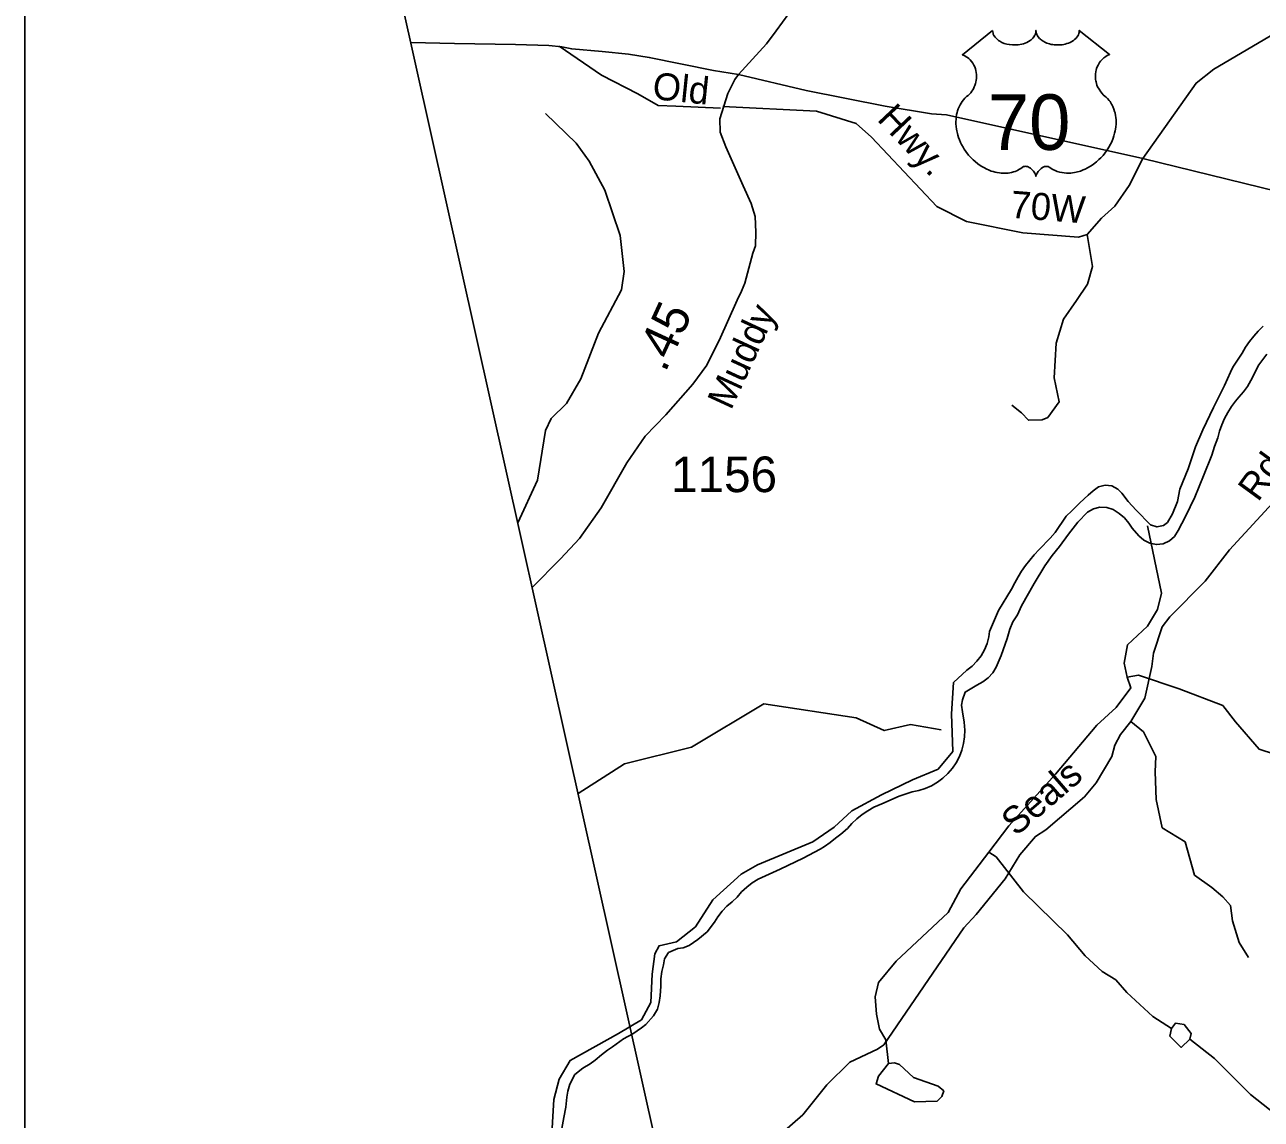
# Model space of a CAD drawing. Extents: x 1113032 to 1302912, y 664689 to 832535.
# Drawn here: x 1147669 to 1152008, y 722592 to 726434 of the extents above; entities that cross this region are included whole.
import ezdxf

# ---------------------------------------------------------------- set-up
doc = ezdxf.new("R2010")
doc.units = 0
for name, color, linetype in [('Exist Boundary Political CountyLine', 7, 'Continuous'), ('Exist Hydrographic Creek Single Shore', 7, 'Continuous'), ('Exist Hydrographic Misc Water Feature', 7, 'Continuous'), ('Exist Hydrographic River Shore', 7, 'Continuous'), ('Exist Road Non-System Type 51', 7, 'Continuous'), ('Exist Road Non-System Type 51 Label', 7, 'Continuous'), ('Exist Road Primary US Attributed', 7, 'Continuous'), ('Exist Road Primary US Shield CELL', 7, 'Continuous'), ('Exist Road Primary US Shield Number Label', 7, 'Continuous'), ('Exist Road Secondary Mileage Hundredths English Label', 7, 'Continuous'), ('Exist Road Secondary Type 51 Attributed', 7, 'Continuous'), ('Exist Road Secondary Type 51 Label', 7, 'Continuous'), ('Exist Road Secondary Type 51 Number Label', 7, 'Continuous'), ('Map Preparation Inset Cut Line', 7, 'Continuous')]:
    doc.layers.add(name, color=color, linetype=linetype)

msp = doc.modelspace()

# ---------------------------------------------------------------- linework, layer by layer
at = {"layer": 'Exist Boundary Political CountyLine'}
msp.add_lwpolyline([(1148404.8, 729149.7), (1156119.1, 694505), (1156385.7, 693318.6), (1156931.2, 691025.8), (1157283.7, 689488.8), (1157952.7, 686675.9), (1158627.6, 683719.1), (1158926.2, 682391.3), (1158990.6, 682053.6), (1159297.9, 680748.3), (1159630.3, 679269.8), (1159949.4, 677817.9), (1160303.4, 676324.9), (1160338.1, 676139.7)], dxfattribs=at)
at = {"layer": 'Exist Hydrographic Creek Single Shore'}
msp.add_lwpolyline([(1149610.4, 723735.3), (1149773.4, 723839.7), (1150008.4, 723897.4), (1150262.3, 724049.9), (1150586.3, 724000.7), (1150685.3, 723956.1), (1150777.3, 723977.2), (1150885.4, 723958.6)], dxfattribs=at)
at = {"layer": 'Exist Hydrographic Misc Water Feature'}
for points in [[(1149496.1, 726121.6), (1149603.3, 726018.5), (1149649.5, 725954.3), (1149704.8, 725853.2), (1149758.3, 725693.7), (1149772.7, 725567.1), (1149762.8, 725503.2), (1149682.5, 725351.4), (1149620, 725191), (1149569.4, 725104.2), (1149515.9, 725051.9), (1149496.8, 725008.9), (1149467.8, 724835.4), (1149399, 724685)], [(1151609.1, 724675.3), (1151658, 724438.7), (1151644.3, 724381.5), (1151608.7, 724322.3), (1151538.8, 724256.5), (1151527, 724192.7), (1151537.6, 724144.1)], [(1151537.6, 724144.1), (1151550.5, 724106.1), (1151498.6, 724037.4), (1151430.7, 723974.7), (1151285.7, 723802.8), (1151122.5, 723621.5), (1151051.9, 723529.4)], [(1152054.3, 723873.6), (1152000.8, 723891.1), (1151917.4, 723987.1), (1151873, 724044.6), (1151720.4, 724102.7), (1151577.8, 724150.7), (1151537.6, 724144.1)], [(1150700.6, 722787.2), (1150691, 722871.1), (1150668, 722907.6), (1150657.5, 722960.4), (1150653.3, 723022), (1150664.6, 723071.8), (1150726.8, 723146.1), (1150909.8, 723317.2), (1150954.2, 723400), (1151051.9, 723529.4)], [(1151692.8, 722910.9), (1151627.9, 722952.4), (1151536.2, 723037.1), (1151497.5, 723080.6), (1151450.3, 723110.2), (1151389.8, 723165.6), (1151327.9, 723239), (1151174.1, 723389.9), (1151077.4, 723512.4), (1151051.9, 723529.4)], [(1151737.2, 722924), (1151707.3, 722928.7), (1151692.8, 722910.9)], [(1151757.8, 722872.7), (1151726.9, 722843.8), (1151688, 722883.1), (1151692.8, 722910.9)], [(1151737.2, 722924), (1151762.3, 722893.1), (1151757.8, 722872.7)], [(1153066.2, 721727.2), (1152995.7, 721708.9), (1152917.7, 721717.9), (1152818.5, 721744.5), (1152617.7, 721860.1), (1152536.6, 721892.1), (1152400.7, 721971.9), (1152298.9, 722053.5), (1152239.4, 722146.6), (1152212.1, 722235.8), (1152202, 722373.9), (1152177.8, 722440.8), (1152103.5, 722572.8), (1151970.4, 722678.8), (1151843.9, 722804.5), (1151757.8, 722872.7)], [(1150700.6, 722787.2), (1150665.3, 722743.6), (1150656.6, 722715.9), (1150790.9, 722652.4), (1150871, 722655.8), (1150887.5, 722671.8), (1150894.1, 722691.4), (1150874.5, 722708.2), (1150787.4, 722738.7), (1150738.6, 722783.9), (1150720.7, 722790), (1150700.6, 722787.2)]]:
    msp.add_lwpolyline(points, dxfattribs=at)
at = {"layer": 'Exist Hydrographic River Shore'}
for points in [[(1151519, 724789), (1151541.6, 724760.7), (1151569.7, 724729.6), (1151619.7, 724678.1), (1151642.1, 724670.8), (1151665.4, 724675.8), (1151679.2, 724687), (1151696.8, 724717.1), (1151714.1, 724760.6), (1151722.3, 724804), (1151751.5, 724875.1), (1151777.4, 724952.6), (1151802.9, 725011.7), (1151840.5, 725090.2), (1151879.3, 725167.5), (1151900.3, 725213.9), (1151908.2, 725231.4), (1151941, 725281.1), (1151953.4, 725301.6), (1151966.9, 725321.5), (1151981.8, 725340.3), (1151997.7, 725358.3), (1152014.8, 725375.2)], [(1152027.9, 725277.3), (1152000, 725239.8), (1151972.1, 725184.7), (1151959.7, 725164.1), (1151945.8, 725144.7), (1151930.1, 725126.5), (1151917.7, 725112.6), (1151903.4, 725093.3), (1151890.6, 725073.1), (1151879.4, 725051.9), (1151869.8, 725029.8), (1151862, 725007.1), (1151856.1, 724983.9), (1151844.3, 724953.3), (1151835.2, 724922.4), (1151805.1, 724850), (1151774.8, 724774.9), (1151742.3, 724707.3), (1151716.1, 724657.8), (1151704, 724637.7), (1151686.1, 724621.8), (1151664.3, 724611.9), (1151640.5, 724609.1), (1151617, 724613.5), (1151595.9, 724624.6), (1151578.9, 724639.3), (1151555.2, 724666.4), (1151543.5, 724684.1), (1151527.9, 724702.3), (1151509.9, 724718.2), (1151489, 724731.6), (1151466.1, 724739), (1151442.3, 724740), (1151419, 724734.5), (1151397.9, 724723.1), (1151364.2, 724687.6), (1151331.5, 724645.8), (1151300.1, 724601.8), (1151274.7, 724570.4), (1151249.2, 724534.6), (1151211.1, 724472.5), (1151166.3, 724394.5), (1151153.3, 724361.9), (1151136.7, 724337.3), (1151125.9, 724311.6), (1151116.9, 724279.1), (1151095.5, 724219.6), (1151078.5, 724178.5), (1151066.1, 724158.9), (1151050, 724141.2), (1151030.9, 724126.8), (1151009.6, 724115.9), (1150969, 724091.3), (1150960.2, 724063.6), (1150956.4, 724045.1)], [(1149516, 722500.5), (1149525.5, 722661.4), (1149544.3, 722732.4), (1149582.3, 722798.6), (1149752.7, 722893.3), (1149833, 722940.6), (1149866.2, 723002.1), (1149870.9, 723101.5), (1149880.4, 723172.5), (1149894.7, 723200.9), (1149956.1, 723215.1), (1150022.4, 723267.1), (1150083.9, 723361.8), (1150183.3, 723451.7), (1150240, 723484.9), (1150434.2, 723565.3), (1150509.7, 723617.4), (1150571.3, 723674.1), (1150675.5, 723730.9), (1150784.3, 723783), (1150874.3, 723820.9), (1150926.3, 723882.4), (1150921.5, 724014.9), (1150928.5, 724125.4), (1150974.7, 724167.9), (1150993.6, 724182.5), (1151010.5, 724199.6), (1151025, 724218.6), (1151036.9, 724239.5), (1151045.9, 724261.7), (1151051.9, 724284.9), (1151054.3, 724303.3), (1151085.6, 724377.6), (1151132.3, 724453), (1151142.9, 724474.5), (1151154.6, 724495.5), (1151167.4, 724515.8), (1151181.2, 724535.4), (1151195.9, 724554.4), (1151211.5, 724572.6), (1151229, 724591.1), (1151267.6, 724631), (1151284.7, 724650.8), (1151323.8, 724708.8), (1151343.3, 724727), (1151371.1, 724755.6), (1151401, 724782.6), (1151418.1, 724797.2), (1151437.4, 724811.2), (1151460.5, 724817.2), (1151484.2, 724814.6), (1151505.3, 724803.6), (1151519, 724789)], [(1150956.4, 724045.1), (1150960.1, 724021.4), (1150965.5, 723985.4), (1150967.9, 723958), (1150967, 723933.9), (1150963.5, 723910.2), (1150957.3, 723887), (1150948.7, 723864.7), (1150937.7, 723843.4), (1150924.1, 723823.6), (1150908.6, 723805.3), (1150891, 723788.9), (1150871.7, 723774.6), (1150851, 723762.5), (1150829.1, 723753), (1150806.2, 723745.7), (1150782.6, 723741.3), (1150737.8, 723725.3), (1150676.4, 723698.9), (1150649, 723686.7), (1150628, 723674.9), (1150608.1, 723661.6), (1150589.3, 723646.7), (1150571.7, 723630.4), (1150555.6, 723612.6), (1150533, 723592.7), (1150514.3, 723577.9), (1150495.3, 723563.2), (1150475.8, 723549.1), (1150460.4, 723539.9), (1150400, 723507.7), (1150346.5, 723482.2), (1150320.3, 723469.9), (1150268.5, 723446), (1150242.6, 723434.4), (1150221.9, 723421.6), (1150202.5, 723406.7), (1150184.7, 723389.7), (1150169, 723370.8), (1150151.3, 723355.4), (1150132.5, 723339.9), (1150115.7, 723322.1), (1150101.3, 723302.5), (1150089.4, 723283.9), (1150063.1, 723250.1), (1150031.2, 723223.1), (1150000, 723201.4), (1149979.9, 723193.5), (1149961.1, 723190.9), (1149928, 723176.8), (1149913.7, 723154.7), (1149910.7, 723133.4), (1149904, 723110.2), (1149901.3, 723085), (1149900.7, 723059.3), (1149898.7, 723024.8), (1149895.6, 723002), (1149889.7, 722978.7), (1149875.5, 722955.1), (1149848.1, 722924.2), (1149833, 722912.8), (1149802.8, 722892.1), (1149769.6, 722874.4), (1149731.8, 722846.5), (1149713.5, 722834.4), (1149692.8, 722818.2), (1149670.1, 722799.7), (1149652.6, 722786.8), (1149626.8, 722771.4), (1149599.3, 722748.5), (1149581.1, 722715.1), (1149574.9, 722690.6), (1149570.6, 722669), (1149568, 722634.6), (1149560.2, 722598.1), (1149553, 722558.8)]]:
    msp.add_lwpolyline(points, dxfattribs=at)
at = {"layer": 'Exist Road Non-System Type 51'}
for points in [[(1152817.2, 726301.2), (1152746.1, 726469.4), (1152721.1, 726516.2), (1152695.7, 726572), (1152611.4, 726632), (1152543.9, 726642.9), (1152476.5, 726637.4), (1152054.9, 726403.1), (1151841.3, 726277.7), (1151779.5, 726228.7), (1151592.9, 725964.1)], [(1150110.6, 726140.7), (1149953.7, 726148), (1149891.7, 726149.6), (1149820.3, 726191.4), (1149693.2, 726257), (1149544, 726358.2)], [(1151397.4, 725696.8), (1151367, 725687.9), (1151171.3, 725703.3), (1150974.2, 725743), (1150869.6, 725796), (1150640.4, 726038.6), (1150586.6, 726087.5), (1150446.9, 726129.7), (1150118.3, 726147.1)], [(1151592.9, 725964.1), (1151544.2, 725868.8), (1151494.2, 725796.3), (1151447.9, 725754.5), (1151397.4, 725696.8)], [(1151133, 725098.7), (1151166.5, 725071.2), (1151190.9, 725045.6), (1151239.6, 725046.8), (1151259.1, 725054.6), (1151298.6, 725109.7), (1151280.9, 725194), (1151288.4, 725316.4), (1151314, 725399.9), (1151360.2, 725465.3), (1151398.7, 725523.1), (1151416.1, 725584.5), (1151397.4, 725696.8)], [(1152334.4, 725152.2), (1152236.3, 725074.7), (1152197.1, 725035.8), (1152177.8, 724990.6), (1152134.4, 724867.7), (1152102.8, 724814.5), (1151896.4, 724590.2), (1151811.2, 724480.6), (1151687.6, 724355.7), (1151660.6, 724320.5), (1151629.8, 724227.6), (1151624.6, 724181.4), (1151599.4, 724070.3), (1151550.8, 723987.6)], [(1151550.8, 723987.6), (1151513.8, 723942.4), (1151494.7, 723905), (1151483.4, 723865.2), (1151428.7, 723772.7), (1151387.4, 723724), (1151252.1, 723607.6), (1151215.5, 723584.7), (1151161.4, 723520.1), (1151109.1, 723435.5), (1151007.5, 723310.5), (1150964.2, 723263.8), (1150684.2, 722853.2), (1150661.9, 722837.8), (1150564.5, 722792.5), (1150484.2, 722712.7), (1150399.3, 722607.1), (1150290.4, 722512.1), (1150119, 722392.8), (1150059.6, 722342.5), (1149950.5, 722208.1)], [(1151963.9, 723159.4), (1151931.2, 723212.2), (1151907.4, 723288.8), (1151900.2, 723341.9), (1151873, 723372.7), (1151835.1, 723404.9), (1151773.7, 723448.7), (1151741.8, 723565.4), (1151660.6, 723615.2), (1151639.2, 723713.9), (1151635.9, 723810.9), (1151638.6, 723864.8), (1151595.5, 723951.5), (1151550.8, 723987.6)]]:
    msp.add_lwpolyline(points, dxfattribs=at)
at = {"layer": 'Exist Road Primary US Attributed'}
for points in [[(1149023.4, 726371.6), (1149177.2, 726367.3), (1149390.6, 726364.6), (1149507.7, 726361.3), (1149553.1, 726356.2), (1149588.5, 726348.6), (1149695.5, 726340.2), (1149787.1, 726330.1), (1149860.4, 726319.2), (1150085.9, 726272.9), (1150173.5, 726258.4)], [(1150173.5, 726258.4), (1150411.1, 726202.9), (1150687.9, 726148.2), (1150851.4, 726120.4), (1150903.6, 726117.9), (1151592.9, 725964.1), (1152065.7, 725848.6), (1152454, 725759.9)]]:
    msp.add_lwpolyline(points, dxfattribs=at)
at = {"layer": 'Exist Road Primary US Shield CELL'}
msp.add_lwpolyline([(1151065.6, 726413.2), (1151065.9, 726408.8), (1151067, 726403.6), (1151067.8, 726400.9), (1151070.2, 726395.7), (1151074.3, 726389.6), (1151079.9, 726383.7), (1151086.2, 726378.4), (1151090.5, 726375.7), (1151097.7, 726371.8), (1151106, 726368.3), (1151115.1, 726365.7), (1151124.5, 726363.8), (1151134.7, 726362.7), (1151144.8, 726362.5), (1151155.7, 726363.3), (1151167.8, 726365.6), (1151173.4, 726367.1), (1151179.6, 726369.2), (1151185.4, 726371.6), (1151191.7, 726375), (1151196.8, 726378.3), (1151200.8, 726381.1), (1151206.4, 726386.5), (1151210.9, 726392.1), (1151212.8, 726395.3), (1151214.4, 726398.3), (1151216.6, 726404.7), (1151217.3, 726407.5), (1151217.7, 726413.4), (1151218.1, 726408.5), (1151218.6, 726405.4), (1151219.4, 726402.4), (1151220.7, 726399.2), (1151222.9, 726394.7), (1151225.4, 726390.9), (1151230.2, 726385.3), (1151233.1, 726382.5), (1151235.8, 726380.3), (1151243, 726375.4), (1151251.5, 726371.1), (1151255.6, 726369.3), (1151259.9, 726367.8), (1151265.3, 726366.1), (1151270.9, 726364.8), (1151276.4, 726363.9), (1151282, 726363.1), (1151287.8, 726362.6), (1151292.5, 726362.5), (1151298.3, 726362.6), (1151303.6, 726362.9), (1151309.1, 726363.5), (1151315.1, 726364.5), (1151320, 726365.6), (1151326.4, 726367.3), (1151332.1, 726369.3), (1151337.2, 726371.5), (1151343.8, 726375), (1151349.1, 726378.3), (1151353, 726381.5), (1151357.7, 726385.7), (1151362.1, 726390.8), (1151364.6, 726394.5), (1151366.5, 726398.4), (1151368.2, 726402.4), (1151369.2, 726406.6), (1151369.7, 726410.4), (1151369.8, 726413.5), (1151476.1, 726328.9), (1151473.6, 726327.9), (1151467.8, 726325.1), (1151463.2, 726322.4), (1151455.9, 726317.2), (1151452.8, 726314.4), (1151449.6, 726311.4), (1151446.7, 726308.3), (1151444.2, 726305.3), (1151441.1, 726301.1), (1151438.4, 726296.8), (1151435.7, 726292.1), (1151433.7, 726288), (1151430.4, 726279.5), (1151428.9, 726274.1), (1151427.8, 726269.5), (1151426.6, 726260), (1151426.3, 726255.5), (1151426.3, 726251), (1151426.5, 726246.3), (1151427, 726241.8), (1151427.8, 726237.1), (1151428.5, 726232.9), (1151429.9, 726227.9), (1151431.7, 726222), (1151434.1, 726216.2), (1151438.9, 726207), (1151445.2, 726197.6), (1151449.6, 726192.3), (1151454, 726187.8), (1151460.6, 726182.3), (1151464.1, 726179.1), (1151468.2, 726175), (1151474.9, 726167.3), (1151477.6, 726163.7), (1151480.3, 726159.6), (1151482.8, 726155.4), (1151485.3, 726150.9), (1151487.3, 726146.9), (1151491.1, 726137.8), (1151493.8, 726128.9), (1151495, 726124.3), (1151497, 726113.9), (1151497.8, 726108.7), (1151498.6, 726098.5), (1151498.6, 726086.2), (1151497.7, 726074.6), (1151495.5, 726060.9), (1151493.7, 726052.8), (1151490.9, 726043.3), (1151488.2, 726035.1), (1151483.3, 726022.9), (1151479, 726014.1), (1151473.4, 726003.9), (1151469.6, 725997.6), (1151465.1, 725991), (1151459.5, 725983.3), (1151453, 725975.2), (1151445.2, 725966.5), (1151438.8, 725960.2), (1151430.5, 725952.8), (1151425.5, 725948.6), (1151418.4, 725943.2), (1151408.6, 725936.7), (1151398.9, 725931.1), (1151390.7, 725926.9), (1151383.4, 725923.8), (1151374, 725920.2), (1151358.3, 725915.9), (1151352.6, 725914.7), (1151345.8, 725913.7), (1151339.5, 725913), (1151333.3, 725912.7), (1151325, 725912.7), (1151316.8, 725913.3), (1151309, 725914.4), (1151300.9, 725916.1), (1151292.5, 725918.6), (1151284.8, 725921.6), (1151277, 725925.5), (1151263.8, 725933.8), (1151260, 725935.8), (1151257.9, 725936.3), (1151252.8, 725936.6), (1151248.1, 725935.6), (1151243.2, 725933.6), (1151240.2, 725932.1), (1151236.3, 725929.5), (1151233.3, 725927.1), (1151229.6, 725923.7), (1151227.1, 725920.8), (1151225.2, 725918.5), (1151221.5, 725912.7), (1151220.2, 725909.9), (1151218.8, 725906.3), (1151217.6, 725901.1), (1151215.9, 725907.7), (1151214, 725912.1), (1151211.7, 725915.9), (1151209.4, 725919.2), (1151205.7, 725923.5), (1151202.3, 725926.7), (1151198.3, 725929.9), (1151194, 725932.5), (1151190.6, 725934.3), (1151187.5, 725935.5), (1151183.7, 725936.4), (1151180.5, 725936.7), (1151177.9, 725936.6), (1151174.4, 725935.8), (1151169.6, 725932.3), (1151165, 725929.2), (1151160.1, 725926.1), (1151154.2, 725923), (1151149.9, 725921), (1151144.7, 725918.9), (1151138.7, 725916.9), (1151132.2, 725915.2), (1151125.4, 725913.9), (1151119.5, 725913), (1151113.2, 725912.4), (1151107.5, 725912.2), (1151101.5, 725912.3), (1151095.9, 725912.7), (1151089.5, 725913.3), (1151081.4, 725914.5), (1151074.8, 725916), (1151067.8, 725917.9), (1151060.5, 725920.1), (1151052.8, 725923.1), (1151043.2, 725927.3), (1151036.4, 725930.8), (1151025.8, 725936.8), (1151013.4, 725945.4), (1151004, 725953), (1150997.1, 725959.3), (1150987, 725969.6), (1150981.1, 725976.3), (1150971.8, 725988.3), (1150965.8, 725997.1), (1150962, 726003.5), (1150956.3, 726013.8), (1150953.2, 726020.2), (1150949.2, 726029.7), (1150946, 726038.3), (1150943.4, 726046.4), (1150942, 726051.6), (1150940, 726060.7), (1150938.7, 726067.2), (1150937.6, 726076.1), (1150936.9, 726085.4), (1150936.8, 726094), (1150937, 726101.2), (1150937.8, 726109.5), (1150939.2, 726118.4), (1150940.9, 726126), (1150942.5, 726131.5), (1150944.7, 726138.1), (1150947.7, 726145.5), (1150951.2, 726152.5), (1150954.6, 726158.3), (1150958.8, 726164.6), (1150962.9, 726170), (1150968.3, 726175.9), (1150974, 726181.3), (1150979.2, 726185.5), (1150985.3, 726191.5), (1150988.5, 726195.1), (1150992.4, 726200.2), (1150995.5, 726204.9), (1150997.9, 726209.1), (1151001.1, 726215.4), (1151003.1, 726220), (1151005.5, 726227.2), (1151006.8, 726232.2), (1151008, 726238.7), (1151008.8, 726244.7), (1151009.1, 726252.3), (1151009, 726258.6), (1151008.1, 726266), (1151006.8, 726273), (1151005.1, 726279.2), (1151002.5, 726286.2), (1151000, 726291.3), (1150996, 726298.3), (1150991.4, 726304.8), (1150986.8, 726310.1), (1150982.1, 726314.8), (1150977.5, 726318.3), (1150973.2, 726321.4), (1150967.8, 726324.6), (1150962.6, 726327.2), (1150959.4, 726328.5)], close=True, dxfattribs=at)
at = {"layer": 'Exist Road Secondary Type 51 Attributed'}
for points in [[(1150173.5, 726258.4), (1150271.3, 726366.3), (1150305.8, 726412.7), (1150461.4, 726626.3), (1150608.8, 726837.6), (1150699.7, 726933.3), (1150802.3, 727028.5), (1150918.6, 727129.7), (1151044.6, 727223.9), (1151178.3, 727320.6), (1151228.8, 727355.2), (1151412.5, 727494.3), (1151615.1, 727696.9), (1151765.7, 727849.1), (1151842.1, 727927)], [(1150173.5, 726258.4), (1150160.8, 726241.5), (1150135.6, 726192.1), (1150108, 726103.7), (1150109.5, 726056.7), (1150129, 726005.2), (1150189.6, 725868.6), (1150218.3, 725805.9), (1150231.8, 725760.3), (1150234.6, 725706), (1150233.5, 725657.7), (1150224.2, 725631.6), (1150196.4, 725527), (1150184.6, 725498.4), (1150168.6, 725467.2), (1150106.2, 725325.1), (1150087.7, 725291.4), (1150062.4, 725239.1), (1150013.6, 725172.1), (1149918.5, 725064.2), (1149846, 724989.2), (1149781.2, 724895.9), (1149692.1, 724738), (1149616.1, 724629.8), (1149548.9, 724558.4), (1149449.3, 724458.8)]]:
    msp.add_lwpolyline(points, dxfattribs=at)
at = {"layer": 'Map Preparation Inset Cut Line'}
msp.add_lwpolyline([(1223351.7, 748878.2), (1147668.5, 748878.2), (1147668.5, 704629.7), (1208143, 704629.7), (1208143, 720169.6), (1223351.7, 720169.6)], close=True, dxfattribs=at)

# ---------------------------------------------------------------- texts
at = {"layer": 'Exist Road Non-System Type 51 Label'}
for s, rotation, p in [('Old', 354.1466, (1149868.9, 726173.1)), ('Hwy.', 313.3734, (1150656.9, 726100.1)), ('70W', 355.4973, (1151125.9, 725756.6)), ('Rd.', 53.879, (1151996.9, 724755.7)), ('Seals', 40.7212, (1151147.4, 723582.4))]:
    msp.add_text(s, height=95, rotation=rotation, dxfattribs=at).set_placement(p)
at = {"layer": 'Exist Road Primary US Shield Number Label'}
msp.add_text('70', height=195, dxfattribs=at).set_placement((1151048.5, 725994.4))
at = {"layer": 'Exist Road Secondary Mileage Hundredths English Label'}
msp.add_text('.45', height=125, rotation=65.2457, dxfattribs=at).set_placement((1149916.3, 725210.3))
at = {"layer": 'Exist Road Secondary Type 51 Label'}
msp.add_text('Muddy', height=95, rotation=65.2457, dxfattribs=at).set_placement((1150147.3, 725077.8))
at = {"layer": 'Exist Road Secondary Type 51 Number Label'}
msp.add_text('1156', height=125, dxfattribs=at).set_placement((1149937.1, 724793))

doc.saveas('drawing.dxf')
